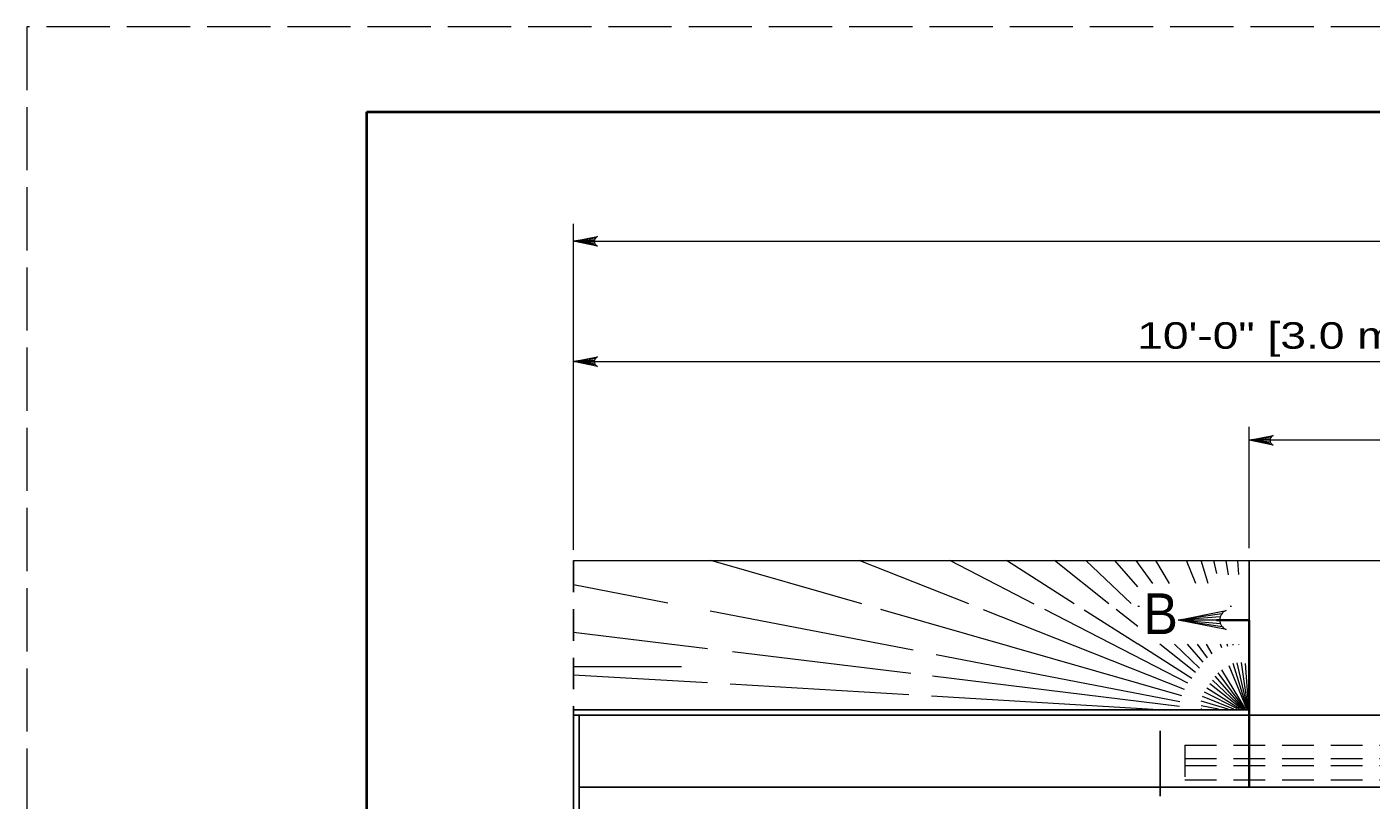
# Model space of a CAD drawing. Extents: x 1083.1 to 1123, y 697.4 to 741.4.
# Drawn here: x 1083.13 to 1091.03, y 736.8 to 741.35 of the extents above; entities that cross this region are included whole.
import ezdxf

# ---------------------------------------------------------------- set-up
doc = ezdxf.new("R2010")
doc.units = 0
doc.header["$LTSCALE"] = 0.062
doc.linetypes.add('LONG_DASHED', pattern=[7.5, 6, -1.5])
doc.linetypes.add('MEDIUM_DASHED', pattern=[4.5, 3, -1.5])
doc.layers.add('1', color=7, linetype='Continuous', lineweight=13)

msp = doc.modelspace()

# ---------------------------------------------------------------- linework, layer by layer
at = {"layer": '1', "lineweight": 25}
for p, q in [((1085.12642, 740.85408), (1116.62642, 740.85408)), ((1086.34158, 737.33458), (1090.31492, 737.33458)), ((1086.34158, 733.92158), (1086.34158, 737.30308)), ((1086.37358, 737.30308), (1086.34475, 737.30308)), ((1086.37358, 733.92158), (1086.37358, 737.30308)), ((1090.31492, 737.30308), (1097.19883, 737.30308)), ((1086.37833, 736.87908), (1096.93425, 736.87908))]:
    msp.add_line(p, q, dxfattribs=at)
at = {"layer": '1'}
for p, q in [((1086.34033, 738.27667), (1086.34033, 740.194)), ((1086.4685, 740.10983), (1086.34033, 740.09192)), ((1086.46417, 740.101), (1086.34033, 740.09192)), ((1086.46283, 740.09192), (1086.34033, 740.09192)), ((1086.46508, 740.08042), (1086.34033, 740.09192)), ((1086.47, 740.07208), (1086.34033, 740.09192)), ((1086.34033, 740.09192), (1102.18317, 740.09192)), ((1086.4685, 739.40183), (1086.34033, 739.38392)), ((1086.46417, 739.393), (1086.34033, 739.38392)), ((1086.46283, 739.38392), (1086.34033, 739.38392)), ((1086.46508, 739.37242), (1086.34033, 739.38392)), ((1086.47, 739.36408), (1086.34033, 739.38392)), ((1086.34033, 739.38392), (1102.18317, 739.38392)), ((1090.31492, 738.286), (1090.31492, 738.99933)), ((1090.44308, 738.93867), (1090.31492, 738.92067)), ((1090.43875, 738.92975), (1090.31492, 738.92067)), ((1098.24367, 738.92067), (1090.31492, 738.92067)), ((1090.43742, 738.92067), (1090.31492, 738.92067)), ((1090.43975, 738.90917), (1090.31492, 738.92067)), ((1090.44467, 738.90092), (1090.31492, 738.92067)), ((1088.03758, 737.9575), (1087.14958, 738.21267)), ((1088.66625, 737.957), (1088.0215, 738.21267)), ((1089.05083, 737.95642), (1088.55475, 738.21267)), ((1089.2865, 737.95875), (1088.88808, 738.21267)), ((1089.48967, 737.95833), (1089.16925, 738.21267)), ((1089.62075, 737.96042), (1089.35433, 738.21267)), ((1089.65925, 738.05792), (1089.52467, 738.21267)), ((1089.74817, 738.0785), (1089.65008, 738.21267)), ((1089.84708, 738.0785), (1089.76617, 738.21267)), ((1090.00025, 738.0785), (1089.94575, 738.21267)), ((1090.07333, 738.0785), (1090.03158, 738.21267)), ((1090.12458, 738.13717), (1090.10725, 738.21267)), ((1090.193, 738.12792), (1090.18042, 738.21267)), ((1090.2545, 738.131), (1090.2485, 738.21267)), ((1086.8965, 737.96267), (1086.3405, 738.06992)), ((1088.33883, 737.68442), (1087.14458, 737.91483)), ((1089.91875, 737.417), (1088.14933, 737.92542)), ((1089.93483, 737.45383), (1088.75242, 737.92283)), ((1089.95325, 737.49), (1089.11242, 737.9245)), ((1089.65925, 737.72108), (1089.34483, 737.9215)), ((1089.65925, 737.82367), (1089.53233, 737.92442)), ((1089.65925, 737.94367), (1089.66967, 737.94367)), ((1090.2035, 737.94367), (1090.21167, 737.94367)), ((1090.15308, 737.89867), (1089.89675, 737.86275)), ((1090.14442, 737.88092), (1089.89675, 737.86275)), ((1090.14175, 737.86275), (1089.89675, 737.86275)), ((1090.14633, 737.83975), (1089.89675, 737.86275)), ((1090.15617, 737.82317), (1089.89675, 737.86275)), ((1090.31492, 737.86275), (1090.31492, 737.33975)), ((1087.12942, 737.6935), (1086.34092, 737.79008)), ((1088.32408, 737.54708), (1087.27675, 737.67542)), ((1089.97692, 737.51858), (1089.66125, 737.71975)), ((1089.99992, 737.55325), (1089.79008, 737.71975)), ((1090.02258, 737.57992), (1089.87483, 737.71975)), ((1090.04433, 737.61458), (1089.95292, 737.71975)), ((1090.06875, 737.63992), (1090.01033, 737.71975)), ((1090.09717, 737.66408), (1090.06358, 737.71975)), ((1090.15467, 737.698), (1090.14583, 737.71975)), ((1090.18908, 737.70717), (1090.18508, 737.71975)), ((1090.221, 737.71475), (1090.21983, 737.71975)), ((1090.25358, 737.71783), (1090.25333, 737.71975)), ((1086.34075, 737.58942), (1086.97592, 737.58942)), ((1089.90792, 737.38167), (1088.47342, 737.65842)), ((1090.30008, 737.33958), (1090.197, 737.59367)), ((1090.30358, 737.33958), (1090.22025, 737.60717)), ((1090.30658, 737.33967), (1090.24458, 737.61142)), ((1090.3095, 737.33967), (1090.26908, 737.61325)), ((1090.31225, 737.33967), (1090.29275, 737.60725)), ((1087.12942, 737.49208), (1086.34125, 737.53883)), ((1089.905, 737.35333), (1088.452, 737.53133)), ((1090.27667, 737.33933), (1090.09825, 737.50825)), ((1090.28333, 737.33942), (1090.11542, 737.53275)), ((1090.28833, 737.3395), (1090.133, 737.552)), ((1090.29292, 737.3395), (1090.15483, 737.56858)), ((1088.3125, 737.42192), (1087.26292, 737.48408)), ((1090.24533, 737.33908), (1090.05208, 737.43892)), ((1090.25833, 737.33917), (1090.06542, 737.46217)), ((1090.26933, 737.33925), (1090.08333, 737.487)), ((1089.78208, 737.33475), (1088.44642, 737.41392)), ((1090.134, 737.338), (1090.0325, 737.35758)), ((1090.19158, 737.33858), (1090.03283, 737.38417)), ((1090.22467, 737.33883), (1090.0405, 737.41192)), ((1086.34158, 737.30308), (1086.37042, 737.30308)), ((1090.03733, 737.33708), (1090.0305, 737.33792)), ((1090.31492, 737.30308), (1090.31492, 736.87908))]:
    msp.add_line(p, q, dxfattribs=at)
at = {"layer": '1', "linetype": 'MEDIUM_DASHED', "lineweight": 25}
msp.add_line((1086.34033, 738.21267), (1086.34158, 737.30308), dxfattribs=at)
at = {"layer": '1', "lineweight": 35}
for p, q in [((1090.21167, 737.86275), (1090.123, 737.86275)), ((1090.31492, 737.86275), (1090.21167, 737.86275))]:
    msp.add_line(p, q, dxfattribs=at)
at = {"layer": '1', "linetype": 'LONG_DASHED', "lineweight": 25}
for p, q in [((1089.79133, 736.83908), (1089.79133, 737.30308)), ((1089.79133, 736.82542), (1089.79133, 736.83908))]:
    msp.add_line(p, q, dxfattribs=at)
at = {"layer": '1', "linetype": 'MEDIUM_DASHED'}
for p, q in [((1089.93733, 737.12525), (1089.93733, 736.92142)), ((1089.93733, 737.12525), (1096.93425, 737.12525)), ((1089.93733, 737.04733), (1096.93425, 737.04733)), ((1089.93733, 737.00592), (1096.93425, 737.00592)), ((1089.93733, 736.92142), (1096.93425, 736.92142))]:
    msp.add_line(p, q, dxfattribs=at)
at = {"layer": '1', "linetype": 'LONG_DASHED'}
msp.add_lwpolyline([(1083.12642, 719.35408), (1117.12642, 719.35408), (1117.12642, 741.35408), (1083.12642, 741.35408)], close=True, dxfattribs=at)
at = {"layer": '1', "lineweight": 25}
for points in [[(1116.62642, 719.85408), (1085.12642, 719.85408), (1085.12642, 740.85408)], [(1086.37042, 737.30308), (1090.31492, 737.30308), (1090.31492, 737.33975), (1090.31492, 738.21267)]]:
    msp.add_lwpolyline(points, dxfattribs=at)
at = {"layer": '1', "lineweight": 40}
msp.add_lwpolyline([(1085.12642, 740.85408), (1116.62642, 740.85408), (1116.62642, 719.85408), (1085.12642, 719.85408)], close=True, dxfattribs=at)
at = {"layer": '1'}
for points in [[(1086.48192, 740.06358), (1086.34033, 740.09192), (1086.48192, 740.12025)], [(1086.48192, 739.35558), (1086.34033, 739.38392), (1086.48192, 739.41225)], [(1090.4565, 738.89242), (1090.31492, 738.92067), (1090.4565, 738.949)], [(1086.34033, 738.21267), (1091.74717, 738.21267), (1091.79, 738.10867)], [(1090.17992, 737.80617), (1089.89675, 737.86275), (1090.17992, 737.91942)]]:
    msp.add_lwpolyline(points, dxfattribs=at)
at = {"layer": '1', "lineweight": 35}
msp.add_lwpolyline([(1090.31492, 737.86275), (1090.31492, 737.33975), (1090.31492, 736.87908)], dxfattribs=at)
at = {"layer": '1'}
for centre, radius in [((1086.49336, 740.09194), 0.03056), ((1086.49336, 739.38394), 0.03056), ((1090.46795, 738.92074), 0.03056), ((1090.20279, 737.86284), 0.06112)]:
    msp.add_arc(centre, radius, 112.08782, 247.91395, dxfattribs=at)

# ---------------------------------------------------------------- texts
for s, height, width, p in [('10\'-0" [3.0 m]', 0.156, 1.3, (1089.6565, 739.4595)), ('B', 0.24, 0.95, (1089.69258, 737.77958))]:
    msp.add_text(s, height=height, dxfattribs=dict(at, width=width)).set_placement(p)

doc.saveas('drawing.dxf')
